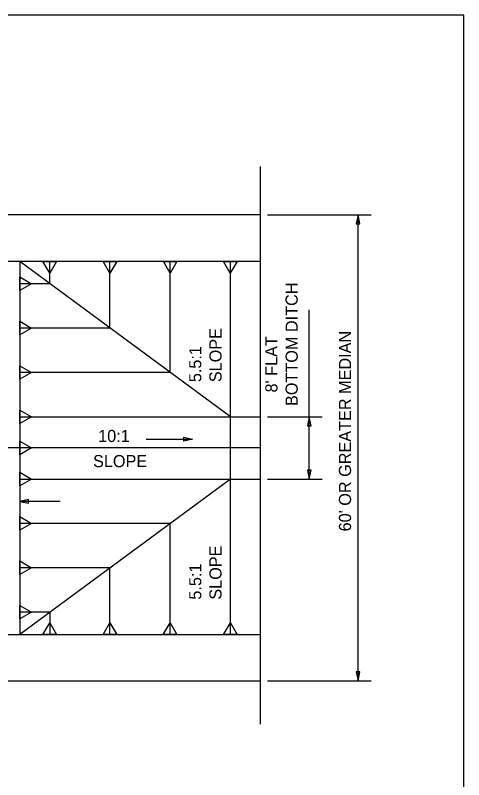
# Model space of a CAD drawing. Extents: x -439.1 to -407.9, y -458.1 to -436.2.
# Drawn here: x -413.4 to -407.86, y -447.12 to -437.68 of the extents above; entities that cross this region are included whole.
import ezdxf

# ---------------------------------------------------------------- set-up
doc = ezdxf.new("R2010")
doc.units = 0
doc.layers.add('Bridge-Named Boundary', color=7, linetype='Continuous')
doc.layers.add('Default', color=7, linetype='Continuous')

msp = doc.modelspace()

# ---------------------------------------------------------------- linework, layer by layer
at = {"layer": 'Bridge-Named Boundary'}
msp.add_lwpolyline([(-439.109, -458.0508), (-407.859, -458.0508), (-407.859, -437.6758), (-439.109, -437.6758)], close=True, dxfattribs=at)
at = {"layer": 'Default'}
for p, q in [((-410.372, -446.4363), (-410.372, -439.5433)), ((-410.372, -440.1433), (-437.226, -440.1433)), ((-410.2844, -440.1434), (-409.0042, -440.1434)), ((-409.1654, -445.9034), (-409.1654, -440.1434)), ((-410.372, -440.7193), (-437.226, -440.7193)), ((-413.348, -440.7193), (-413.348, -445.3273)), ((-410.744, -442.6393), (-413.348, -440.7193)), ((-412.976, -440.9936), (-412.976, -440.7193)), ((-412.232, -441.5422), (-412.232, -440.7193)), ((-411.488, -442.0908), (-411.488, -440.7193)), ((-410.744, -445.3273), (-410.744, -440.7193)), ((-412.976, -440.9936), (-413.348, -440.9936)), ((-409.7683, -442.6394), (-409.7683, -441.3162)), ((-412.232, -441.5422), (-413.348, -441.5422)), ((-411.488, -442.0908), (-413.348, -442.0908)), ((-413.348, -442.6393), (-410.372, -442.6393)), ((-410.2844, -442.6394), (-409.6071, -442.6394)), ((-409.7683, -443.4074), (-409.7683, -442.6394)), ((-411.7836, -442.9149), (-411.2098, -442.9149)), ((-413.348, -443.0233), (-434.25, -443.0233)), ((-410.372, -443.0233), (-413.348, -443.0233)), ((-413.348, -443.4073), (-410.372, -443.4073)), ((-410.744, -443.4073), (-413.348, -445.3273)), ((-410.2844, -443.4074), (-409.6071, -443.4074)), ((-412.8492, -443.6847), (-413.348, -443.6847)), ((-411.488, -443.9559), (-413.348, -443.9559)), ((-411.488, -445.3273), (-411.488, -443.9559)), ((-412.232, -444.5045), (-413.348, -444.5045)), ((-412.232, -445.3273), (-412.232, -444.5045)), ((-412.976, -445.053), (-413.348, -445.053)), ((-412.976, -445.053), (-412.976, -445.3273)), ((-437.226, -445.3273), (-410.372, -445.3273)), ((-437.226, -445.9033), (-410.372, -445.9033)), ((-410.2844, -445.9034), (-409.0042, -445.9034))]:
    msp.add_line(p, q, dxfattribs=at)
for points in [[(-409.1424, -440.254), (-409.1654, -440.1434), (-409.1883, -440.254)], [(-413.06, -440.719), (-412.892, -440.7197), (-412.9765, -440.8648)], [(-412.316, -440.719), (-412.148, -440.7197), (-412.2325, -440.8648)], [(-411.572, -440.719), (-411.404, -440.7197), (-411.4885, -440.8648)], [(-410.828, -440.719), (-410.66, -440.7197), (-410.7445, -440.8648)], [(-413.348, -440.9096), (-413.2025, -440.9936), (-413.348, -441.0776)], [(-413.348, -441.4582), (-413.2025, -441.5422), (-413.348, -441.6262)], [(-413.348, -442.0068), (-413.2025, -442.0908), (-413.348, -442.1748)], [(-413.348, -442.5553), (-413.2025, -442.6393), (-413.348, -442.7233)], [(-409.7453, -442.75), (-409.7683, -442.6394), (-409.7912, -442.75)], [(-411.3205, -442.8919), (-411.2098, -442.9149), (-411.3205, -442.9379)], [(-413.348, -442.9393), (-413.2025, -443.0233), (-413.348, -443.1073)], [(-409.7912, -443.2967), (-409.7683, -443.4074), (-409.7453, -443.2967)], [(-413.348, -443.3233), (-413.2025, -443.4073), (-413.348, -443.4913)], [(-413.2373, -443.6618), (-413.348, -443.6847), (-413.2373, -443.7077)], [(-413.348, -443.8719), (-413.2025, -443.9559), (-413.348, -444.0399)], [(-413.348, -444.4205), (-413.2025, -444.5045), (-413.348, -444.5885)], [(-413.348, -444.969), (-413.2025, -445.0531), (-413.348, -445.137)], [(-413.0605, -445.3287), (-412.9758, -445.1836), (-412.8925, -445.3295)], [(-412.3165, -445.3287), (-412.2318, -445.1836), (-412.1485, -445.3295)], [(-411.5725, -445.3287), (-411.4878, -445.1836), (-411.4045, -445.3295)], [(-410.8285, -445.3287), (-410.7438, -445.1836), (-410.6605, -445.3295)], [(-409.1883, -445.7927), (-409.1654, -445.9034), (-409.1424, -445.7927)]]:
    msp.add_lwpolyline(points, close=True, dxfattribs=at)

# ---------------------------------------------------------------- texts
for s, p in [('BOTTOM DITCH', (-409.9112, -442.505)), ('SLOPE', (-410.8528, -442.2106)), ("60' OR GREATER MEDIAN", (-409.2516, -444.0549)), ("   8' FLAT", (-410.1612, -442.505)), ('5.5:1 ', (-411.1028, -442.2106)), ('SLOPE', (-410.8528, -444.8986)), ('5.5:1 ', (-411.1028, -444.8986))]:
    msp.add_text(s, height=0.15, rotation=90, dxfattribs=at).set_placement(p)
for s, p in [('10:1', (-412.378, -442.9504)), ('SLOPE', (-412.4411, -443.261))]:
    msp.add_text(s, height=0.15, dxfattribs=at).set_placement(p)

doc.saveas('drawing.dxf')
